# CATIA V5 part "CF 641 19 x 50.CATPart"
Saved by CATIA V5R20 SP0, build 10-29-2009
Part number: CF 641 19 x 50
Definition: NONE
Nomenclature: CF 641 19 x 50
Source: Unknown
Description: CF 641 19 x 50
Bounding box of the stored display mesh (mm): x -32 to 18, y -17 to 17, z -17 to 17
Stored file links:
  C:\Users\Utente\Desktop\IO LAVORO\3D X SITO CF\X SITO\CF 641\CF 641 19 x 50.CATPart
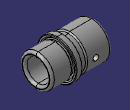
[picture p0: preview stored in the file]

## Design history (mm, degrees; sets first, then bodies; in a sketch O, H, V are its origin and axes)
Body1 "CF 641 19 x 50" (main body)
  Solid1: solid without history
